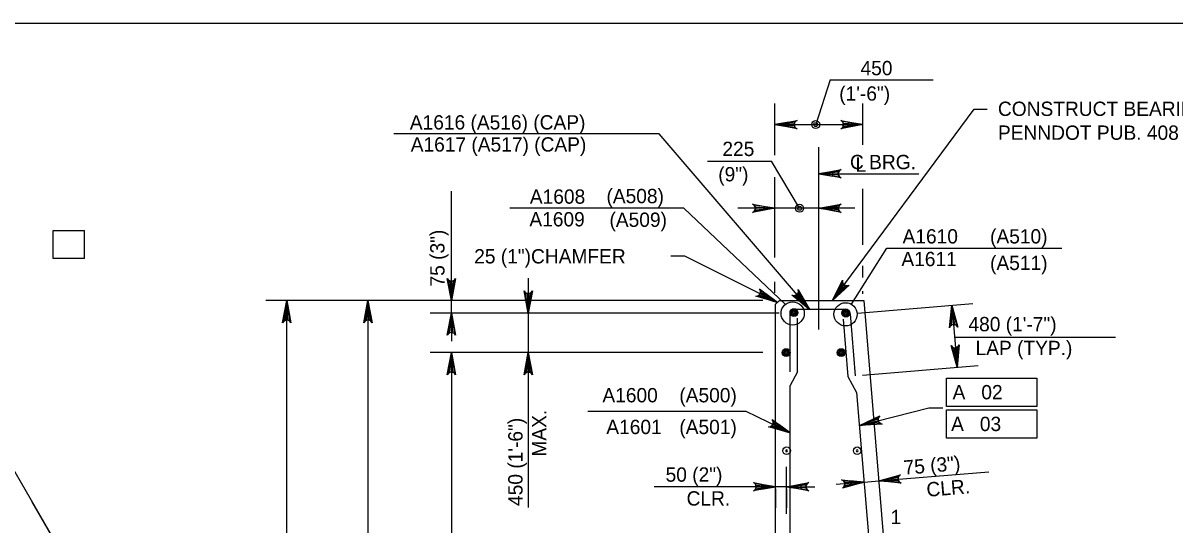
# Model space of a CAD drawing. Extents: x 638340 to 640241, y 295465 to 298435.
# Drawn here: x 638939.7 to 639181.1, y 297127.3 to 297232.5 of the extents above; entities that cross this region are included whole.
import ezdxf

# ---------------------------------------------------------------- set-up
doc = ezdxf.new("R2010")
doc.units = 0
for name, color, linetype in [('2', 7, 'Continuous'), ('3', 7, 'Continuous'), ('4', 7, 'Continuous'), ('5', 7, 'Continuous'), ('9', 7, 'Continuous')]:
    doc.layers.add(name, color=color, linetype=linetype)

# ---------------------------------------------------------------- blocks, each defined once
blk = doc.blocks.new('B')
at = {"layer": '3'}
blk.add_circle((0, 0), 0.16, dxfattribs=at)
for start, end in [(0, 180), (180, 0)]:
    blk.add_arc((0, 0), 0.0391, start, end, dxfattribs=at)

msp = doc.modelspace()

# ---------------------------------------------------------------- linework, layer by layer
at = {"layer": '2'}
msp.add_line((638475.46, 297232.46), (639261.46, 297232.46), dxfattribs=at)
at = {"layer": '3'}
for p, q in [((639108.84, 297220.55), (639105.8, 297211.19)), ((639108.84, 297220.55), (639130.42, 297220.55)), ((639097.22, 297204.76), (639097.22, 297215.62)), ((639109.35, 297174.31), (639139, 297214.44)), ((639115.69, 297206.94), (639115.69, 297215.62)), ((639139, 297214.44), (639141.75, 297214.44)), ((639097.22, 297206.23), (639097.22, 297211.93)), ((639097.23, 297211.19), (639115.69, 297211.19)), ((639115.69, 297211.19), (639115.69, 297211.19)), ((639073, 297209.23), (639017.44, 297209.23)), ((639104.49, 297172.49), (639073, 297209.23)), ((639106.45, 297168.27), (639106.45, 297206.46)), ((639083.14, 297203.55), (639096.56, 297203.55)), ((639102.42, 297193.65), (639096.56, 297203.55)), ((639097.22, 297183.36), (639097.22, 297200.14)), ((639106.45, 297200.88), (639127.43, 297200.88)), ((639097.23, 297193.67), (639097.23, 297198.37)), ((639097.23, 297195.06), (639097.23, 297198.08)), ((639115.69, 297185.98), (639115.69, 297197.71)), ((639029.48, 297171.7), (639029.48, 297197.2)), ((639113.99, 297193.65), (639089.49, 297193.65)), ((638946.02, 297183.12), (638946.02, 297189.02)), ((638946.02, 297189.02), (638952.61, 297189.02)), ((638952.61, 297183.12), (638952.61, 297189.02)), ((638952.61, 297183.12), (638946.02, 297183.12)), ((639078.38, 297183.62), (639075.43, 297183.62)), ((639097.8, 297173.93), (639078.38, 297183.62)), ((639115.69, 297179.16), (639115.69, 297181.59)), ((639029.48, 297174.31), (639029.48, 297180.22)), ((639045.57, 297179), (639045.57, 297130.97)), ((639097.22, 297175.93), (639097.22, 297178.24)), ((639115.69, 297175.7), (639115.69, 297176.28)), ((639024.34, 297174.31), (638990.56, 297174.31)), ((638994.99, 297005.79), (638994.99, 297174.31)), ((639094.71, 297174.31), (639007.56, 297174.31)), ((639011.99, 297174.31), (639011.99, 297105.67)), ((639011.99, 297174.31), (639011.99, 297174.31)), ((639059.58, 297174.31), (639025.05, 297174.31)), ((639114.54, 297171.67), (639138.74, 297173.69)), ((639134.32, 297173.32), (639135.41, 297160.33)), ((639098.16, 297171.7), (639025.05, 297171.7)), ((639029.48, 297171.7), (639029.48, 297165.79)), ((638919.46, 297170.52), (638947.13, 297122.59)), ((639134.88, 297166.67), (639168.64, 297166.67)), ((639094.74, 297163.4), (639025.05, 297163.4)), ((639029.48, 297163.4), (639029.48, 297039.86)), ((639115.63, 297158.68), (639139.82, 297160.7)), ((639133.18, 297152.14), (639133.18, 297158.04)), ((639133.18, 297158.04), (639152.13, 297158.04)), ((639152.13, 297158.04), (639152.13, 297152.14)), ((639114.96, 297148.14), (639129.49, 297151.85)), ((639129.49, 297151.85), (639132.44, 297151.85)), ((639152.13, 297152.14), (639133.18, 297152.14)), ((639091.26, 297151.09), (639058.09, 297151.09)), ((639100.48, 297146.57), (639091.26, 297151.09)), ((639133.18, 297151.39), (639152.13, 297151.39)), ((639133.18, 297145.49), (639133.18, 297151.39)), ((639152.13, 297151.39), (639152.13, 297145.49)), ((639152.13, 297145.49), (639133.18, 297145.49)), ((639097.41, 297136.56), (639097.41, 297139.5)), ((639099.7, 297129.61), (639099.7, 297139.5)), ((639124.9, 297137.03), (639142.09, 297138.46)), ((639091.5, 297135.3), (639071.98, 297135.3)), ((639094.46, 297135.3), (639091.5, 297135.3)), ((639099.7, 297135.3), (639097.41, 297135.3)), ((639097.41, 297134.87), (639097.41, 297130.87)), ((639099.7, 297134.87), (639099.7, 297130.87)), ((639102.65, 297135.3), (639105.6, 297135.3)), ((639115.95, 297136.28), (639110.06, 297135.79)), ((639115.95, 297136.28), (639119.01, 297136.54)), ((639119.01, 297136.54), (639124.9, 297137.03)), ((638941.59, 297132.18), (638954.12, 297110.49))]:
    msp.add_line(p, q, dxfattribs=at)
for points in [[(639097.23, 297211.19), (639101.89, 297212.06), (639101.53, 297211.81), (639101.34, 297211.5), (639101.29, 297211.19), (639101.34, 297210.87), (639101.53, 297210.56), (639101.89, 297210.31), (639097.23, 297211.19), (639101.53, 297210.56), (639101.34, 297210.87), (639097.23, 297211.19), (639101.29, 297211.19), (639101.34, 297211.5), (639097.23, 297211.19), (639101.53, 297211.81)], [(639097.23, 297211.19), (639101.89, 297212.06), (639101.53, 297211.81), (639101.34, 297211.5), (639101.29, 297211.19), (639101.34, 297210.87), (639101.53, 297210.56), (639101.89, 297210.31), (639097.23, 297211.19), (639101.53, 297210.56), (639101.34, 297210.87), (639097.23, 297211.19), (639101.29, 297211.19), (639101.34, 297211.5), (639097.23, 297211.19), (639101.53, 297211.81)], [(639115.69, 297211.19), (639111.03, 297210.31), (639111.39, 297210.56), (639111.57, 297210.87), (639111.63, 297211.19), (639111.57, 297211.5), (639111.39, 297211.81), (639111.03, 297212.06), (639115.69, 297211.19), (639111.39, 297211.81), (639111.57, 297211.5), (639115.69, 297211.19), (639111.63, 297211.19), (639111.57, 297210.87), (639115.69, 297211.19), (639111.39, 297210.56)], [(639106.45, 297200.88), (639111.12, 297201.76), (639110.76, 297201.51), (639110.57, 297201.2), (639110.52, 297200.88), (639110.57, 297200.57), (639110.76, 297200.26), (639111.12, 297200.01), (639106.45, 297200.88), (639110.76, 297200.26), (639110.57, 297200.57), (639106.45, 297200.88), (639110.52, 297200.88), (639110.57, 297201.2), (639106.45, 297200.88), (639110.76, 297201.51)], [(639097.23, 297193.65), (639092.56, 297192.78), (639092.92, 297193.03), (639093.11, 297193.34), (639093.16, 297193.65), (639093.11, 297193.97), (639092.92, 297194.28), (639092.56, 297194.53), (639097.23, 297193.65), (639092.92, 297194.28), (639093.11, 297193.97), (639097.23, 297193.65), (639093.16, 297193.65), (639093.11, 297193.34), (639097.23, 297193.65), (639092.92, 297193.03)], [(639106.45, 297193.65), (639111.12, 297194.53), (639110.76, 297194.28), (639110.57, 297193.97), (639110.52, 297193.65), (639110.57, 297193.34), (639110.76, 297193.03), (639111.12, 297192.78), (639106.45, 297193.65), (639110.76, 297193.03), (639110.57, 297193.34), (639106.45, 297193.65), (639110.52, 297193.65), (639110.57, 297193.97), (639106.45, 297193.65), (639110.76, 297194.28)], [(639029.48, 297174.31), (639028.61, 297178.97), (639028.86, 297178.61), (639029.17, 297178.43), (639029.48, 297178.38), (639029.79, 297178.43), (639030.11, 297178.61), (639030.35, 297178.97), (639029.48, 297174.31), (639030.11, 297178.61), (639029.79, 297178.43), (639029.48, 297174.31), (639029.48, 297178.38), (639029.17, 297178.43), (639029.48, 297174.31), (639028.86, 297178.61)], [(639109.35, 297174.31), (639111.42, 297178.58), (639111.4, 297178.15), (639111.55, 297177.81), (639111.77, 297177.58), (639112.05, 297177.44), (639112.41, 297177.4), (639112.82, 297177.54), (639109.35, 297174.31), (639112.41, 297177.4), (639112.05, 297177.44), (639109.35, 297174.31), (639111.77, 297177.58), (639111.55, 297177.81), (639109.35, 297174.31), (639111.4, 297178.15)], [(639045.57, 297171.7), (639044.7, 297176.36), (639044.95, 297176), (639045.26, 297175.81), (639045.57, 297175.76), (639045.89, 297175.81), (639046.2, 297176), (639046.45, 297176.36), (639045.57, 297171.7), (639046.2, 297176), (639045.89, 297175.81), (639045.57, 297171.7), (639045.57, 297175.76), (639045.26, 297175.81), (639045.57, 297171.7), (639044.95, 297176)], [(639097.8, 297173.93), (639093.24, 297175.23), (639093.67, 297175.29), (639093.97, 297175.49), (639094.16, 297175.75), (639094.25, 297176.05), (639094.23, 297176.41), (639094.02, 297176.79), (639097.8, 297173.93), (639094.23, 297176.41), (639094.25, 297176.05), (639097.8, 297173.93), (639094.16, 297175.75), (639093.97, 297175.49), (639097.8, 297173.93), (639093.67, 297175.29)], [(639104.49, 297172.49), (639100.79, 297175.46), (639101.21, 297175.35), (639101.57, 297175.41), (639101.84, 297175.57), (639102.04, 297175.82), (639102.16, 297176.16), (639102.12, 297176.6), (639104.49, 297172.49), (639102.16, 297176.16), (639102.04, 297175.82), (639104.49, 297172.49), (639101.84, 297175.57), (639101.57, 297175.41), (639104.49, 297172.49), (639101.21, 297175.35)], [(638994.99, 297174.31), (638995.86, 297169.65), (638995.61, 297170.01), (638995.3, 297170.2), (638994.99, 297170.25), (638994.68, 297170.2), (638994.36, 297170.01), (638994.12, 297169.65), (638994.99, 297174.31), (638994.36, 297170.01), (638994.68, 297170.2), (638994.99, 297174.31), (638994.99, 297170.25), (638995.3, 297170.2), (638994.99, 297174.31), (638995.61, 297170.01)], [(639011.99, 297174.31), (639012.87, 297169.65), (639012.62, 297170.01), (639012.31, 297170.2), (639011.99, 297170.25), (639011.68, 297170.2), (639011.37, 297170.01), (639011.12, 297169.65), (639011.99, 297174.31), (639011.37, 297170.01), (639011.68, 297170.2), (639011.99, 297174.31), (639011.99, 297170.25), (639012.31, 297170.2), (639011.99, 297174.31), (639012.62, 297170.01)], [(639134.32, 297173.32), (639135.58, 297168.75), (639135.3, 297169.09), (639134.98, 297169.25), (639134.66, 297169.27), (639134.35, 297169.2), (639134.06, 297168.99), (639133.84, 297168.61), (639134.32, 297173.32), (639134.06, 297168.99), (639134.35, 297169.2), (639134.32, 297173.32), (639134.66, 297169.27), (639134.98, 297169.25), (639134.32, 297173.32), (639135.3, 297169.09)], [(639029.48, 297171.7), (639030.35, 297167.03), (639030.11, 297167.39), (639029.79, 297167.58), (639029.48, 297167.63), (639029.17, 297167.58), (639028.86, 297167.39), (639028.61, 297167.03), (639029.48, 297171.7), (639028.86, 297167.39), (639029.17, 297167.58), (639029.48, 297171.7), (639029.48, 297167.63), (639029.79, 297167.58), (639029.48, 297171.7), (639030.11, 297167.39)], [(639135.41, 297160.33), (639134.15, 297164.9), (639134.43, 297164.56), (639134.75, 297164.4), (639135.07, 297164.37), (639135.38, 297164.45), (639135.67, 297164.66), (639135.89, 297165.04), (639135.41, 297160.33), (639135.67, 297164.66), (639135.38, 297164.45), (639135.41, 297160.33), (639135.07, 297164.37), (639134.75, 297164.4), (639135.41, 297160.33), (639134.43, 297164.56)], [(639029.48, 297163.4), (639030.35, 297158.74), (639030.11, 297159.1), (639029.79, 297159.29), (639029.48, 297159.34), (639029.17, 297159.29), (639028.86, 297159.1), (639028.61, 297158.74), (639029.48, 297163.4), (639028.86, 297159.1), (639029.17, 297159.29), (639029.48, 297163.4), (639029.48, 297159.34), (639029.79, 297159.29), (639029.48, 297163.4), (639030.11, 297159.1)], [(639045.57, 297163.4), (639046.45, 297158.74), (639046.2, 297159.1), (639045.89, 297159.29), (639045.57, 297159.34), (639045.26, 297159.29), (639044.95, 297159.1), (639044.7, 297158.74), (639045.57, 297163.4), (639044.95, 297159.1), (639045.26, 297159.29), (639045.57, 297163.4), (639045.57, 297159.34), (639045.89, 297159.29), (639045.57, 297163.4), (639046.2, 297159.1)], [(639100.48, 297146.57), (639095.91, 297147.84), (639096.34, 297147.91), (639096.64, 297148.11), (639096.83, 297148.36), (639096.92, 297148.67), (639096.89, 297149.03), (639096.68, 297149.41), (639100.48, 297146.57), (639096.89, 297149.03), (639096.92, 297148.67), (639100.48, 297146.57), (639096.83, 297148.36), (639096.64, 297148.11), (639100.48, 297146.57), (639096.34, 297147.91)], [(639114.96, 297148.14), (639119.26, 297150.14), (639118.97, 297149.81), (639118.87, 297149.47), (639118.89, 297149.15), (639119.02, 297148.86), (639119.28, 297148.6), (639119.69, 297148.45), (639114.96, 297148.14), (639119.28, 297148.6), (639119.02, 297148.86), (639114.96, 297148.14), (639118.89, 297149.15), (639118.87, 297149.47), (639114.96, 297148.14), (639118.97, 297149.81)], [(639119.01, 297136.54), (639123.58, 297137.8), (639123.25, 297137.52), (639123.09, 297137.19), (639123.06, 297136.88), (639123.14, 297136.57), (639123.35, 297136.27), (639123.73, 297136.05), (639119.01, 297136.54), (639123.35, 297136.27), (639123.14, 297136.57), (639119.01, 297136.54), (639123.06, 297136.88), (639123.09, 297137.19), (639119.01, 297136.54), (639123.25, 297137.52)], [(639097.41, 297135.3), (639092.75, 297134.43), (639093.11, 297134.68), (639093.29, 297134.99), (639093.35, 297135.3), (639093.29, 297135.61), (639093.11, 297135.93), (639092.75, 297136.18), (639097.41, 297135.3), (639093.11, 297135.93), (639093.29, 297135.61), (639097.41, 297135.3), (639093.35, 297135.3), (639093.29, 297134.99), (639097.41, 297135.3), (639093.11, 297134.68)], [(639099.7, 297135.3), (639104.36, 297136.18), (639104, 297135.93), (639103.82, 297135.61), (639103.76, 297135.3), (639103.82, 297134.99), (639104, 297134.68), (639104.36, 297134.43), (639099.7, 297135.3), (639104, 297134.68), (639103.82, 297134.99), (639099.7, 297135.3), (639103.76, 297135.3), (639103.82, 297135.61), (639099.7, 297135.3), (639104, 297135.93)], [(639115.95, 297136.28), (639111.38, 297135.03), (639111.72, 297135.3), (639111.87, 297135.63), (639111.9, 297135.95), (639111.82, 297136.25), (639111.61, 297136.55), (639111.23, 297136.77), (639115.95, 297136.28), (639111.61, 297136.55), (639111.82, 297136.25), (639115.95, 297136.28), (639111.9, 297135.95), (639111.87, 297135.63), (639115.95, 297136.28), (639111.72, 297135.3)]]:
    msp.add_lwpolyline(points, dxfattribs=at)
for points in [[(639100.18, 297210.7), (639100.18, 297211.68), (639097.23, 297211.19)], [(639100.18, 297210.7), (639100.18, 297211.68), (639097.23, 297211.19)], [(639112.74, 297210.7), (639112.74, 297211.68), (639115.69, 297211.19)], [(639109.41, 297200.39), (639109.41, 297201.38), (639106.45, 297200.88)], [(639028.99, 297177.27), (639029.97, 297177.27), (639029.48, 297174.31)], [(638994.5, 297171.36), (638995.48, 297171.36), (638994.99, 297174.31)], [(639012.49, 297171.36), (639011.5, 297171.36), (639011.99, 297174.31)], [(639095.37, 297175.69), (639094.93, 297174.81), (639097.8, 297173.93)], [(639102.93, 297175.06), (639102.17, 297174.43), (639104.45, 297172.49)], [(639135.06, 297170.42), (639134.08, 297170.34), (639134.32, 297173.32)], [(639028.99, 297168.74), (639029.97, 297168.74), (639029.48, 297171.7)], [(639028.99, 297160.45), (639029.97, 297160.45), (639029.48, 297163.4)], [(639135.65, 297163.31), (639134.67, 297163.23), (639135.41, 297160.33)], [(639118.16, 297148.45), (639117.91, 297149.4), (639115.17, 297148.2)], [(639098.04, 297148.32), (639097.61, 297147.43), (639100.48, 297146.57)], [(639121.92, 297137.27), (639122, 297136.29), (639119.01, 297136.54)], [(639094.46, 297135.79), (639094.46, 297134.81), (639097.41, 297135.3)], [(639102.65, 297135.79), (639102.65, 297134.81), (639099.7, 297135.3)], [(639112.97, 297136.53), (639113.05, 297135.55), (639115.95, 297136.28)]]:
    msp.add_lwpolyline(points, close=True, dxfattribs=at)
for centre, radius in [((639105.8, 297211.19), 0.833), ((639105.8, 297211.19), 0.417), ((639102.42, 297193.65), 0.833), ((639102.42, 297193.65), 0.417)]:
    msp.add_circle(centre, radius, dxfattribs=at)
at = {"layer": '4'}
for p, q in [((639078.17, 297193.65), (639041.72, 297193.65)), ((639099.44, 297173.5), (639078.17, 297193.65)), ((639113.29, 297173.54), (639120.68, 297185.26)), ((639120.68, 297185.26), (639157.37, 297185.26))]:
    msp.add_line(p, q, dxfattribs=at)
for centre in [(639100.97, 297171.62), (639112.06, 297171.43)]:
    msp.add_circle(centre, 2.43, dxfattribs=at)
at = {"layer": '5'}
for p, q in [((639100.48, 297159.38), (639100.48, 297171.46)), ((639101.5, 297172.49), (639111.99, 297172.49)), ((639113.01, 297171.55), (639114.09, 297158.55)), ((639102.01, 297159.38), (639102.01, 297170.64)), ((639111.56, 297170.45), (639112.56, 297158.42)), ((639102.01, 297159.38), (639100.48, 297156.54)), ((639100.48, 297082.58), (639100.48, 297156.54)), ((639112.56, 297158.42), (639114.38, 297155.06)), ((639114.38, 297155.06), (639117.99, 297111.77))]:
    msp.add_line(p, q, dxfattribs=at)
for centre, radius in [((639101.25, 297171.78), 0.833), ((639101.25, 297171.78), 0.625), ((639101.25, 297171.78), 0.417), ((639101.25, 297171.78), 0.208), ((639112.13, 297171.7), 0.833), ((639112.13, 297171.7), 0.625), ((639112.13, 297171.7), 0.417), ((639112.13, 297171.7), 0.208), ((639099.61, 297163.4), 0.833), ((639099.61, 297163.4), 0.625), ((639099.61, 297163.4), 0.417), ((639111.14, 297163.4), 0.833), ((639111.14, 297163.4), 0.625), ((639111.14, 297163.4), 0.417), ((639099.61, 297163.4), 0.208), ((639111.14, 297163.4), 0.208)]:
    msp.add_circle(centre, radius, dxfattribs=at)
for centre, start, end in [((639101.5, 297171.46), 90, 180), ((639111.99, 297171.46), 4.7636, 90)]:
    msp.add_arc(centre, 1.03, start, end, dxfattribs=at)
at = {"layer": '9'}
for p, q in [((639097.41, 297173.55), (639098.18, 297174.31)), ((639097.41, 297075.75), (639097.41, 297173.55)), ((639098.18, 297174.31), (639115.87, 297174.31)), ((639115.87, 297174.31), (639127.28, 297037.29))]:
    msp.add_line(p, q, dxfattribs=at)

# ---------------------------------------------------------------- block references
at = {"layer": '3', "xscale": 4.921475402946, "yscale": 4.921475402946, "rotation": 90}
for p in [(639099.7, 297142.85), (639114.49, 297142.85)]:
    msp.add_blockref('B', p, dxfattribs=at)

# ---------------------------------------------------------------- texts
at = {"layer": '3'}
for s, height, p in [('450', 3, (639115.19, 297221.52)), ('(1\'-6")', 3, (639110.73, 297216.2)), ('CONSTRUCT BEARING AREAS AS PER', 3.0001, (639143.98, 297212.99)), ('A1616 (A516) (CAP)', 3.0001, (639020.76, 297210.15)), ('PENNDOT PUB. 408 1001.3(k)8.', 3.0001, (639143.98, 297207.99)), ('A1617 (A517) (CAP)', 3.0001, (639020.95, 297205.52)), ('225', 3, (639086.25, 297204.59)), ('C BRG.', 3, (639112.98, 297201.84)), ('(9")', 3, (639085.38, 297199.28)), ('L', 3, (639114.14, 297201.29)), ('A1608', 3, (639045.91, 297194.6)), ('(A508)', 3, (639061.96, 297194.71)), ('A1609', 3, (639045.81, 297189.85)), ('(A509)', 3, (639062.59, 297189.75)), ('A1610', 3, (639124, 297186.27)), ('(A510)', 3, (639142.33, 297186.27)), ('25 (1")CHAMFER', 3.0001, (639034.25, 297182.09)), ('A1611', 3, (639123.75, 297181.52)), ('(A511)', 3, (639142.33, 297180.71)), ('480 (1\'-7")', 3.0001, (639137.8, 297167.88)), ('LAP (TYP.)', 3, (639139.29, 297162.88)), ('A   02', 3, (639134.48, 297153.62)), ('A1600', 3, (639061.11, 297152.99)), ('(A500)', 3, (639077.23, 297152.99)), ('A1601', 3, (639061.93, 297146.34)), ('(A501)', 3, (639077.23, 297146.34)), ('A   03', 3, (639134.17, 297146.97)), ('50 (2")', 3, (639074.35, 297136.36)), ('CLR.', 3, (639078.75, 297131.36)), ('1', 3, (639121.5, 297127.47))]:
    msp.add_text(s, height=height, dxfattribs=at).set_placement(p)
for s, height, rotation, p in [('75 (3")', 3, 90, (639028.03, 297177.26)), ('450 (1\'-6")', 3.0001, 90, (639044.38, 297131.28)), ('MAX.', 3, 90, (639049.38, 297141.62)), ('75 (3")', 3, 4.7636, (639124.34, 297137.81)), ('CLR.', 3, 4.7636, (639129.13, 297133.19))]:
    msp.add_text(s, height=height, rotation=rotation, dxfattribs=at).set_placement(p)

doc.saveas('drawing.dxf')
